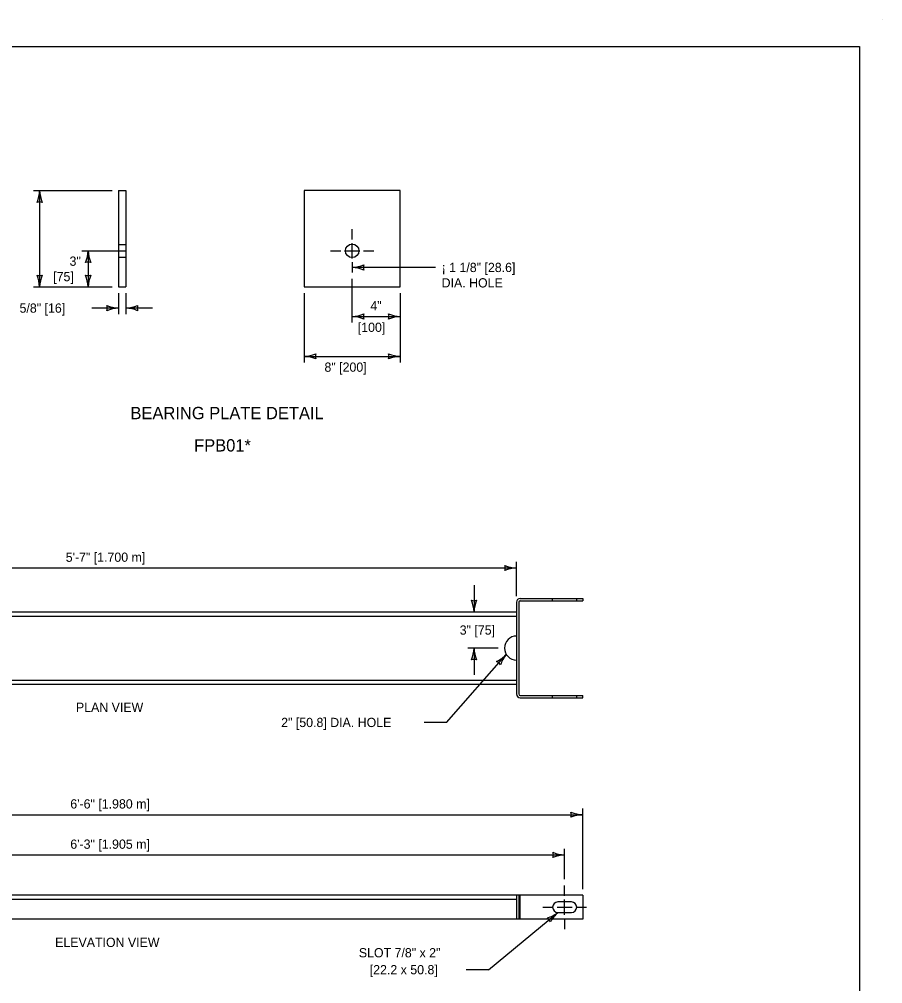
# Model space of a CAD drawing. Extents: x 49991.4 to 50021, y 49987.6 to 50011.4.
# Drawn here: x 50011.29 to 50016.9, y 49992.92 to 49999.18 of the extents above; entities that cross this region are included whole.
import ezdxf

# ---------------------------------------------------------------- set-up
doc = ezdxf.new("R2010")
doc.units = 0
for name, color, linetype in [('Level 1', 7, 'Continuous'), ('Level 2', 7, 'Continuous'), ('Level 3', 7, 'Continuous'), ('Level 4', 7, 'Continuous'), ('Level 5', 7, 'Continuous')]:
    doc.layers.add(name, color=color, linetype=linetype)

msp = doc.modelspace()

# ---------------------------------------------------------------- linework, layer by layer
at = {"layer": 'Level 1'}
for p, q in [((50016.9001, 49999.1756), (50016.9001, 49999.1756)), ((50011.9381, 49998.0633), (50011.9381, 49997.4382)), ((50011.9381, 49998.0633), (50011.9869, 49998.0633)), ((50011.9869, 49998.0633), (50011.9869, 49997.4382)), ((50013.7683, 49998.0633), (50013.1433, 49998.0633)), ((50013.1433, 49998.0633), (50013.1433, 49997.4382)), ((50013.7683, 49997.4382), (50013.7683, 49998.0633)), ((50011.9381, 49997.4382), (50011.9869, 49997.4382)), ((50013.1433, 49997.4382), (50013.7683, 49997.4382)), ((50014.5227, 49995.3917), (50014.5227, 49994.7962)), ((50014.5373, 49995.3917), (50014.5373, 49994.7962)), ((50014.5471, 49995.4161), (50014.9522, 49995.4161)), ((50014.5471, 49995.4015), (50014.9522, 49995.4015)), ((50014.9522, 49995.4161), (50014.9522, 49995.4015)), ((50009.29, 49995.3283), (50014.5227, 49995.3283)), ((50014.5227, 49995.3283), (50014.5227, 49995.1721)), ((50014.5227, 49995.0159), (50014.5227, 49994.8597)), ((50009.29, 49994.8597), (50014.5227, 49994.8597)), ((50014.5471, 49994.7864), (50014.9522, 49994.7864)), ((50014.5471, 49994.7718), (50014.9522, 49994.7718)), ((50014.9522, 49994.7718), (50014.9522, 49994.7864)), ((50014.9522, 49993.49), (50008.8604, 49993.49)), ((50014.5227, 49993.49), (50014.5227, 49993.3338)), ((50014.5471, 49993.3338), (50014.5471, 49993.49)), ((50014.879, 49993.4461), (50014.7911, 49993.4461)), ((50014.9522, 49993.49), (50014.9522, 49993.3338)), ((50014.9522, 49993.3338), (50008.8604, 49993.3338)), ((50014.7911, 49993.3777), (50014.879, 49993.3777))]:
    msp.add_line(p, q, dxfattribs=at)
msp.add_lwpolyline([(49999.3835, 49998.9992), (50016.7501, 49998.9992), (50016.7501, 49987.7988), (49999.3835, 49987.7988)], close=True, dxfattribs=at)
msp.add_circle((50013.4557, 49997.6726), 0.044, dxfattribs=at)
for centre, radius, start, end in [((50014.5471, 49995.3917), 0.0244, 90, 180), ((50014.5471, 49995.3917), 0.00976, 90, 180), ((50014.5227, 49995.094), 0.0781, 90, 270), ((50014.5471, 49994.7962), 0.0244, 180, 270), ((50014.5471, 49994.7962), 0.00976, 180, 270), ((50014.7911, 49993.4119), 0.0342, 90, 270), ((50014.879, 49993.4119), 0.0342, 270, 90)]:
    msp.add_arc(centre, radius, start, end, dxfattribs=at)
at = {"layer": 'Level 3'}
for p, q in [((50011.3864, 49998.0633), (50011.8981, 49998.0633)), ((50011.4264, 49998.0633), (50011.4264, 49997.4382)), ((50011.7414, 49997.6726), (50011.7414, 49997.4382)), ((50013.9965, 49997.5648), (50013.4557, 49997.5648)), ((50013.4556, 49997.2063), (50013.4557, 49997.4911)), ((50011.3864, 49997.4382), (50011.8981, 49997.4382)), ((50011.9381, 49997.3982), (50011.9381, 49997.2609)), ((50011.9869, 49997.3982), (50011.9869, 49997.2609)), ((50013.1433, 49997.3982), (50013.1433, 49996.9476)), ((50013.7683, 49997.3982), (50013.7683, 49996.9476)), ((50011.9381, 49997.3009), (50011.7647, 49997.3009)), ((50012.1604, 49997.3009), (50011.9869, 49997.3009)), ((50013.4556, 49997.2463), (50013.7683, 49997.2463)), ((50013.1433, 49996.9876), (50013.7683, 49996.9876)), ((50014.5227, 49995.4317), (50014.5228, 49995.654)), ((50009.2901, 49995.614), (50014.5228, 49995.614)), ((50014.2467, 49995.5017), (50014.2467, 49995.3283)), ((50014.4046, 49995.094), (50014.2067, 49995.094)), ((50014.2467, 49995.094), (50014.2467, 49994.9206)), ((50014.0672, 49994.6113), (50014.4564, 49995.0527)), ((50014.0672, 49994.6113), (50013.9223, 49994.6113)), ((50008.8604, 49994.0126), (50014.9522, 49994.0126)), ((50014.9522, 49993.53), (50014.9522, 49994.0526)), ((50014.8351, 49993.5934), (50014.8352, 49993.7913)), ((50008.9776, 49993.7513), (50014.8351, 49993.7513)), ((50014.3409, 49993.0064), (50014.7911, 49993.3777)), ((50014.3409, 49993.0064), (50014.196, 49993.0064))]:
    msp.add_line(p, q, dxfattribs=at)
for centre, radius, start, end in [((50011.2043, 49998.0724), 0.2223, 337.45601, 357.63952), ((50011.6591, 49998.0747), 0.233, 182.82731, 202.07716), ((50011.4264, 49997.935), 0.0548, 72.13882, 107.86118), ((50011.5193, 49997.6817), 0.2223, 337.45601, 357.63952), ((50011.9741, 49997.6841), 0.233, 182.82731, 202.07716), ((50011.7414, 49997.5444), 0.0548, 72.13882, 107.86118), ((50013.4442, 49997.7975), 0.233, 272.82731, 292.07716), ((50013.5839, 49997.5648), 0.0548, 162.13882, 197.86118), ((50011.4264, 49997.5664), 0.0548, 252.13882, 287.86118), ((50011.1937, 49997.4267), 0.233, 2.82731, 22.07716), ((50011.6485, 49997.429), 0.2223, 157.45601, 177.63952), ((50011.7414, 49997.5664), 0.0548, 252.13882, 287.86118), ((50011.5087, 49997.4267), 0.233, 2.82731, 22.07716), ((50011.9636, 49997.429), 0.2223, 157.45601, 177.63952), ((50013.4466, 49997.3426), 0.2223, 67.45601, 87.63952), ((50011.9472, 49997.523), 0.2223, 247.45601, 267.63952), ((50011.8099, 49997.3009), 0.0548, 342.13882, 17.86118), ((50011.9496, 49997.0681), 0.233, 92.82731, 112.07716), ((50011.9754, 49997.5336), 0.233, 272.82731, 292.07716), ((50011.9778, 49997.0787), 0.2223, 67.45601, 87.63952), ((50012.1151, 49997.3009), 0.0548, 162.13882, 197.86118), ((50013.4465, 49997.4684), 0.2223, 272.36048, 292.54399), ((50013.4441, 49997.0135), 0.233, 67.92284, 87.17269), ((50013.5838, 49997.2463), 0.0548, 162.13882, 197.86118), ((50013.6401, 49997.2463), 0.0548, 342.13882, 17.86118), ((50013.7798, 49997.479), 0.233, 247.92284, 267.17269), ((50013.7774, 49997.0241), 0.2223, 92.36048, 112.54399), ((50013.1318, 49997.2203), 0.233, 272.82731, 292.07716), ((50013.1341, 49996.7654), 0.2223, 67.45601, 87.63952), ((50013.2715, 49996.9876), 0.0548, 162.13882, 197.86118), ((50013.7774, 49997.2097), 0.2223, 247.45601, 267.63952), ((50013.6401, 49996.9876), 0.0548, 342.13882, 17.86118), ((50013.7798, 49996.7548), 0.233, 92.82731, 112.07716), ((50014.5319, 49995.8361), 0.2223, 247.45601, 267.63952), ((50014.3945, 49995.614), 0.0548, 342.13882, 17.86118), ((50014.5343, 49995.3813), 0.233, 92.82731, 112.07716), ((50014.2467, 49995.4565), 0.0548, 252.13882, 287.86118), ((50014.014, 49995.3168), 0.233, 2.82731, 22.07716), ((50014.4688, 49995.3191), 0.2223, 157.45601, 177.63952), ((50014.0246, 49995.1032), 0.2223, 337.45601, 357.63952), ((50014.4794, 49995.1055), 0.233, 182.82731, 202.07716), ((50014.2467, 49994.9658), 0.0548, 72.13882, 107.86118), ((50014.2958, 49995.2064), 0.2223, 296.05076, 316.23427), ((50014.6385, 49994.9074), 0.233, 141.42206, 160.67191), ((50014.3716, 49994.9565), 0.0548, 30.73357, 66.45593), ((50014.9614, 49994.2348), 0.2223, 247.45601, 267.63952), ((50014.824, 49994.0126), 0.0548, 342.13882, 17.86118), ((50014.9637, 49993.7799), 0.233, 92.82731, 112.07716), ((50014.8442, 49993.9735), 0.2223, 247.45601, 267.63952), ((50014.7069, 49993.7513), 0.0548, 342.13882, 17.86118), ((50014.8466, 49993.5186), 0.233, 92.82731, 112.07716), ((50014.6569, 49993.5549), 0.2223, 286.97595, 307.15946), ((50014.6922, 49993.2961), 0.0548, 21.65876, 57.38112), ((50014.9481, 49993.2055), 0.233, 132.34725, 151.5971)]:
    msp.add_arc(centre, radius, start, end, dxfattribs=at)
at = {"layer": 'Level 4'}
for p, q in [((50011.9381, 49997.7141), (50011.9869, 49997.7141)), ((50011.9381, 49997.6311), (50011.9869, 49997.6311)), ((50014.757, 49995.4015), (50014.757, 49995.4161)), ((50014.9132, 49995.4015), (50014.9132, 49995.4161)), ((50009.29, 49995.3015), (50014.5227, 49995.3015)), ((50009.29, 49994.8864), (50014.5227, 49994.8864)), ((50014.757, 49994.7718), (50014.757, 49994.7864)), ((50014.9132, 49994.7718), (50014.9132, 49994.7864)), ((50009.29, 49993.4632), (50014.5227, 49993.4632)), ((50014.5373, 49993.49), (50014.5373, 49993.3338))]:
    msp.add_line(p, q, dxfattribs=at)
at = {"layer": 'Level 5'}
for p, q in [((50013.4557, 49997.7467), (50013.4557, 49997.8141)), ((50013.4557, 49997.6234), (50013.4557, 49997.7217)), ((50011.7014, 49997.6726), (50011.9869, 49997.6726)), ((50013.3142, 49997.6726), (50013.3816, 49997.6726)), ((50013.4066, 49997.6726), (50013.5049, 49997.6726)), ((50013.5299, 49997.6726), (50013.5973, 49997.6726)), ((50013.4557, 49997.5984), (50013.4557, 49997.5311)), ((50014.8351, 49993.486), (50014.8351, 49993.5534)), ((50014.8351, 49993.3628), (50014.8351, 49993.461)), ((50014.6935, 49993.4119), (50014.7609, 49993.4119)), ((50014.7859, 49993.4119), (50014.8842, 49993.4119)), ((50014.9092, 49993.4119), (50014.9766, 49993.4119)), ((50014.8351, 49993.3378), (50014.8351, 49993.2704))]:
    msp.add_line(p, q, dxfattribs=at)

# ---------------------------------------------------------------- texts
at = {"layer": 'Level 2'}
for s, height, p in [('3"', 0.06, (50011.6207, 49997.5755)), ('¡ 1 1/8" [28.6]', 0.06, (50014.0365, 49997.5348)), ('[75]', 0.06, (50011.5149, 49997.4753)), ('DIA. HOLE', 0.06, (50014.0365, 49997.4348)), (' 5/8" [16]', 0.06, (50011.274, 49997.2709)), ('4"', 0.06, (50013.5739, 49997.2863)), ('[100]', 0.06, (50013.4922, 49997.1463)), ('8" [200]', 0.06, (50013.2758, 49996.8876)), ('BEARING PLATE DETAIL', 0.08, (50012.0164, 49996.5797)), ('FPB01*', 0.08, (50012.4296, 49996.3699)), ('5\'-7" [1.700 m]', 0.06, (50011.596, 49995.654)), ('3" [75]', 0.06, (50014.1539, 49995.1812)), ('PLAN VIEW', 0.06, (50011.6624, 49994.6797)), ('2" [50.8] DIA. HOLE', 0.06, (50012.9948, 49994.5813)), ('6\'-6" [1.980 m]', 0.06, (50011.6257, 49994.0526)), ('6\'-3" [1.905 m]', 0.06, (50011.6257, 49993.7913)), ('ELEVATION VIEW', 0.06, (50011.5273, 49993.1538)), ('SLOT 7/8" x 2"', 0.06, (50013.499, 49993.0864)), ('[22.2 x 50.8]', 0.06, (50013.5699, 49992.9764))]:
    msp.add_text(s, height=height, dxfattribs=at).set_placement(p)

doc.saveas('drawing.dxf')
